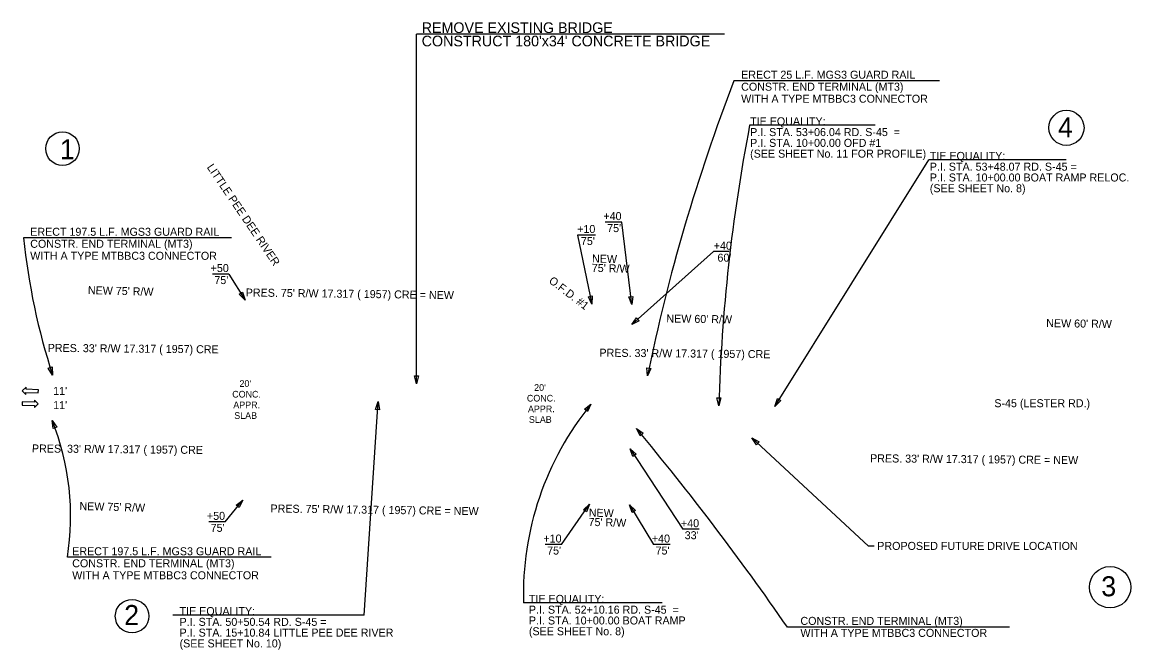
# Model space of a CAD drawing. Extents: x -3336 to 3318, y -3606 to 6276.
# Drawn here: x -16 to 815, y 1151 to 1621 of the extents above; entities that cross this region are included whole.
import ezdxf

# ---------------------------------------------------------------- set-up
doc = ezdxf.new("R2010")
doc.units = 0
for name, color, linetype in [('RD_EX_DV_TX_Prop', 7, 'Continuous'), ('RD_EX_RW_TX', 7, 'Continuous'), ('RD_HC_Data', 7, 'Continuous'), ('RD_PD_Driveway_TX', 7, 'Continuous'), ('RD_PD_Final_LnLine', 7, 'Continuous'), ('RD_PD_Final_TX', 7, 'Continuous'), ('RD_PD_RW', 7, 'Continuous'), ('RD_PD_RW_TX', 7, 'Continuous'), ('RD_TX_Drainage', 7, 'Continuous'), ('RD_TX_Misc1', 7, 'Continuous'), ('RD_TX_RoadID', 7, 'Continuous')]:
    doc.layers.add(name, color=color, linetype=linetype)

msp = doc.modelspace()

# ---------------------------------------------------------------- linework, layer by layer
at = {"layer": 'RD_EX_DV_TX_Prop'}
for centre, radius in [((766.58, 1542.19), 13.16), ((13.94, 1526.57), 12.57), ((799.32, 1197.82), 15.51), ((66.13, 1176.12), 12.57)]:
    msp.add_circle(centre, radius, dxfattribs=at)
at = {"layer": 'RD_HC_Data'}
for p, q in [((623.07, 1544.08), (529.09, 1544.08)), ((548.03, 1333.36), (663.43, 1518.13)), ((766.45, 1518.13), (663.43, 1518.13)), ((240.15, 1176.93), (250.52, 1336.91)), ((618.12, 1228.63), (530.75, 1309.82)), ((622.37, 1228.63), (618.12, 1228.63)), ((463.55, 1186.05), (359.59, 1186.05)), ((240.15, 1176.93), (96.73, 1176.93))]:
    msp.add_line(p, q, dxfattribs=at)
for centre, radius, start, end in [((1808.04, 1297.24), 1302.55, 169.07612, 178.38866), ((585.18, 1192.56), 225.69, 140.86318, 181.65341)]:
    msp.add_arc(centre, radius, start, end, dxfattribs=at)
at = {"layer": 'RD_PD_Final_LnLine'}
for points in [[(-4.27, 1343.42), (-4.16, 1345.81), (-13.32, 1346.22), (-13.25, 1347.84), (-16.2, 1345.14), (-13.5, 1342.19), (-13.43, 1343.82)], [(-16.23, 1336.67), (-16.28, 1334.27), (-7.11, 1334.1), (-7.14, 1332.47), (-4.26, 1335.25), (-7.03, 1338.13), (-7.06, 1336.5)]]:
    msp.add_lwpolyline(points, close=True, dxfattribs=at)
at = {"layer": 'RD_PD_Final_TX'}
for p in [(510.23, 1612.35), (279.43, 1350.33)]:
    msp.add_line(p, (279.43, 1612.35), dxfattribs=at)
at = {"layer": 'RD_PD_RW'}
for p, q in [((433.15, 1471.51), (420.78, 1471.51)), ((440.86, 1409.65), (433.15, 1471.51)), ((413.48, 1461.83), (400.13, 1461.83)), ((400.13, 1461.83), (410.87, 1410)), ((440.69, 1394.65), (502.01, 1449.35)), ((513.74, 1449.35), (502.01, 1449.35)), ((138.72, 1432.56), (126.33, 1432.56)), ((138.72, 1432.56), (150.88, 1413.11)), ((439.57, 1301.65), (478.92, 1241.29)), ((135.88, 1246.81), (149.09, 1263.12)), ((388.16, 1229.8), (409.08, 1260.02)), ((439.07, 1259.66), (457.1, 1229.8)), ((135.88, 1246.81), (123.55, 1246.81)), ((491.29, 1241.29), (478.92, 1241.29)), ((388.16, 1229.8), (375.79, 1229.8)), ((469.47, 1229.8), (457.1, 1229.8))]:
    msp.add_line(p, q, dxfattribs=at)
at = {"layer": 'RD_TX_Drainage'}
for points in [[(148.98, 1418.99), (150.88, 1413.11), (146.43, 1417.4)], [(411.12, 1416.18), (410.87, 1410), (408.18, 1415.58)], [(441.61, 1415.79), (440.86, 1409.65), (438.63, 1415.41)], [(446.16, 1397.52), (440.69, 1394.65), (444.16, 1399.76)], [(6.12, 1363), (6.55, 1356.83), (3.26, 1362.07)], [(280.93, 1356.33), (279.43, 1350.33), (277.93, 1356.33)], [(455.07, 1361.74), (452.41, 1356.15), (452.13, 1362.33)], [(507.58, 1339.84), (506, 1333.86), (504.58, 1339.88)], [(552.48, 1337.66), (548.03, 1333.36), (549.94, 1339.25)], [(248.64, 1331.02), (250.52, 1336.91), (251.63, 1330.83)], [(405.18, 1331.3), (410.13, 1335.01), (407.51, 1329.41)], [(7, 1316.71), (6.15, 1322.83), (9.78, 1317.83)], [(447.04, 1311.25), (444.24, 1316.77), (449.31, 1313.22)], [(534.12, 1304.64), (530.75, 1309.82), (536.17, 1306.84)], [(441.59, 1295.81), (439.57, 1301.65), (444.11, 1297.45)], [(144.15, 1259.4), (149.09, 1263.12), (146.48, 1257.51)], [(404.43, 1255.94), (409.08, 1260.02), (406.89, 1254.23)], [(440.89, 1253.75), (439.07, 1259.66), (443.46, 1255.3)]]:
    msp.add_lwpolyline(points, close=True, dxfattribs=at)
at = {"layer": 'RD_TX_Misc1'}
for p, q in [((671.42, 1577.45), (517.31, 1577.45)), ((140.74, 1459.76), (-15.24, 1459.76)), ((170.41, 1220.33), (17.63, 1220.33)), ((723.99, 1167.78), (557.38, 1167.78))]:
    msp.add_line(p, q, dxfattribs=at)
for centre, radius, start, end in [((1821.66, 1074.75), 1397.86, 158.92309, 168.38632), ((474.3, 1509.63), 492.07, 185.81721, 198.0912), ((-172.11, 1250.97), 192.19, 350.82568, 21.95645), ((-1147.62, -9.56), 2072, 34.62598, 39.80095)]:
    msp.add_arc(centre, radius, start, end, dxfattribs=at)

# ---------------------------------------------------------------- texts
at = {"layer": 'RD_EX_DV_TX_Prop'}
for s, p in [('4', (760.18, 1535.06)), ('1', (12.01, 1518.6)), ('3', (792.7, 1191.02)), ('2', (60.21, 1169.46))]:
    msp.add_text(s, height=15, dxfattribs=at).set_placement(p)
at = {"layer": 'RD_EX_RW_TX'}
for s, rotation, p in [("PRES. 75' R/W 17.317 ( 1957) CRE = NEW", 359.26228, (151.31, 1415.77)), ("PRES. 33' R/W 17.317 ( 1957) CRE", 359.47622, (2.86, 1374.26)), ("PRES. 33' R/W 17.317 ( 1957) CRE", 359.47622, (416.46, 1370.64)), ("PRES. 33' R/W 17.317 ( 1957) CRE", 359.47622, (-8.97, 1298.87)), ("PRES. 33' R/W 17.317 ( 1957) CRE = NEW", 359.47622, (619.35, 1291.49)), ("PRES. 75' R/W 17.317 ( 1957) CRE = NEW", 359.26228, (169.85, 1253.85))]:
    msp.add_text(s, height=6, rotation=rotation, dxfattribs=at).set_placement(p)
at = {"layer": 'RD_HC_Data'}
for s, p in [('TIE EQUALITY:', (529.43, 1544.08)), ('P.I. STA. 53+06.04 RD. S-45  =', (529.43, 1535.99)), ('P.I. STA. 10+00.00 OFD #1', (529.43, 1527.91)), ('(SEE SHEET No. 11 FOR PROFILE)', (529.43, 1519.83)), ('TIE EQUALITY:', (664.13, 1518.13)), ('P.I. STA. 53+48.07 RD. S-45 =', (664.13, 1510.05)), ('P.I. STA. 10+00.00 BOAT RAMP RELOC.', (664.13, 1501.97)), ('(SEE SHEET No. 8)', (664.13, 1493.89)), ('PROPOSED FUTURE DRIVE LOCATION', (624.76, 1225.78)), ('TIE EQUALITY:', (363.6, 1186.05)), ('TIE EQUALITY:', (101.73, 1176.93)), ('P.I. STA. 52+10.16 RD. S-45  =', (363.6, 1177.97)), ('P.I. STA. 50+50.54 RD. S-45 =', (101.73, 1168.85)), ('P.I. STA. 10+00.00 BOAT RAMP', (363.6, 1169.89)), ('P.I. STA. 15+10.84 LITTLE PEE DEE RIVER', (101.73, 1160.77)), ('(SEE SHEET No. 8)', (363.6, 1161.8)), ('(SEE SHEET No. 10)', (101.73, 1152.69))]:
    msp.add_text(s, height=6, dxfattribs=at).set_placement(p)
at = {"layer": 'RD_PD_Driveway_TX'}
for p in [(6.97, 1341.97), (6.97, 1331.32)]:
    msp.add_text("11'", height=6, dxfattribs=at).set_placement(p)
at = {"layer": 'RD_PD_Final_TX'}
for s, height, p in [('REMOVE EXISTING BRIDGE', 8, (283.22, 1613.26)), ("CONSTRUCT 180'x34' CONCRETE BRIDGE", 8, (283.22, 1603.26)), ("20'", 5, (146.62, 1348)), ("20'", 5, (367.52, 1345.01)), ('CONC.', 5, (141.19, 1340)), ('CONC.', 5, (362.09, 1337.01)), ('APPR.', 5, (142.01, 1332)), ('APPR.', 5, (362.9, 1329.01)), ('SLAB', 5, (142.71, 1324)), ('SLAB', 5, (363.6, 1321.01))]:
    msp.add_text(s, height=height, dxfattribs=at).set_placement(p)
at = {"layer": 'RD_PD_RW'}
for s, p in [('+40', (419.44, 1473.01)), ('+10', (399.78, 1463.33)), ("75'", (422.26, 1464.01)), ("75'", (402.59, 1454.33)), ('+40', (502.15, 1450.85)), ("60'", (504.96, 1441.85)), ('+50', (124.99, 1434.06)), ("75'", (127.81, 1425.06)), ('+50', (122.21, 1248.31)), ('+40', (477.58, 1242.79)), ("75'", (125.03, 1239.31)), ("33'", (480.4, 1233.79)), ('+10', (374.46, 1231.3)), ('+40', (455.77, 1231.3)), ("75'", (377.27, 1222.3)), ("75'", (458.58, 1222.3))]:
    msp.add_text(s, height=6, dxfattribs=at).set_placement(p)
at = {"layer": 'RD_PD_RW_TX'}
for s, rotation, p in [('NEW', 358.53354, (410.87, 1441.26)), ("75' R/W", 358.53354, (410.69, 1434.26)), ("NEW 75' R/W", 358.53354, (32.91, 1417.53)), ("NEW 60' R/W", 359.19099, (466.65, 1396.27)), ("NEW 60' R/W", 359.19099, (751.37, 1392.83)), ("NEW 75' R/W", 358.53354, (26.61, 1255.67)), ('NEW', 358.53354, (408.43, 1250.78)), ("75' R/W", 358.53354, (408.25, 1243.78))]:
    msp.add_text(s, height=6, rotation=rotation, dxfattribs=at).set_placement(p)
at = {"layer": 'RD_TX_Misc1'}
for s, p in [('ERECT 25 L.F. MGS3 GUARD RAIL', (522.71, 1579)), ('CONSTR. END TERMINAL (MT3)', (522.71, 1570)), ('WITH A TYPE MTBBC3 CONNECTOR', (522.71, 1561)), ('ERECT 197.5 L.F. MGS3 GUARD RAIL', (-10.24, 1461.26)), ('CONSTR. END TERMINAL (MT3)', (-10.24, 1452.26)), ('WITH A TYPE MTBBC3 CONNECTOR', (-10.24, 1443.26)), ('ERECT 197.5 L.F. MGS3 GUARD RAIL', (21.23, 1221.76)), ('CONSTR. END TERMINAL (MT3)', (21.23, 1212.76)), ('WITH A TYPE MTBBC3 CONNECTOR', (21.23, 1203.76)), ('CONSTR. END TERMINAL (MT3)', (567.16, 1169.57)), ('WITH A TYPE MTBBC3 CONNECTOR', (567.16, 1160.57))]:
    msp.add_text(s, height=6, dxfattribs=at).set_placement(p)
at = {"layer": 'RD_TX_RoadID'}
for s, rotation, p in [('LITTLE PEE DEE RIVER', 304.13067, (121.9, 1512.62)), ('O.F.D. #1', 322.50382, (378.02, 1426.51))]:
    msp.add_text(s, height=6, rotation=rotation, dxfattribs=at).set_placement(p)
msp.add_text('S-45 (LESTER RD.)', height=6, dxfattribs=at).set_placement((712.51, 1332.75))

doc.saveas('drawing.dxf')
